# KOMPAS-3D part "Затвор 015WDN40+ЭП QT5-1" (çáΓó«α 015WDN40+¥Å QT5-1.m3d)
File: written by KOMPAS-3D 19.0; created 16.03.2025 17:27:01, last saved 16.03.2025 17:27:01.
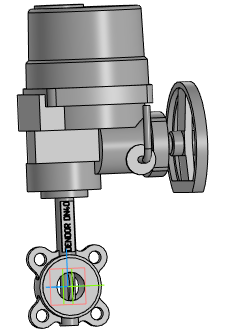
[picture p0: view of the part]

Document properties: Полное имя файла: Затвор 015WDN40+ЭП QT5-1.a3d

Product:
- Part/product: Затвор 015WDN40+ЭП QT5-1
    Масса: 42.069

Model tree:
1. Операция без истории:1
